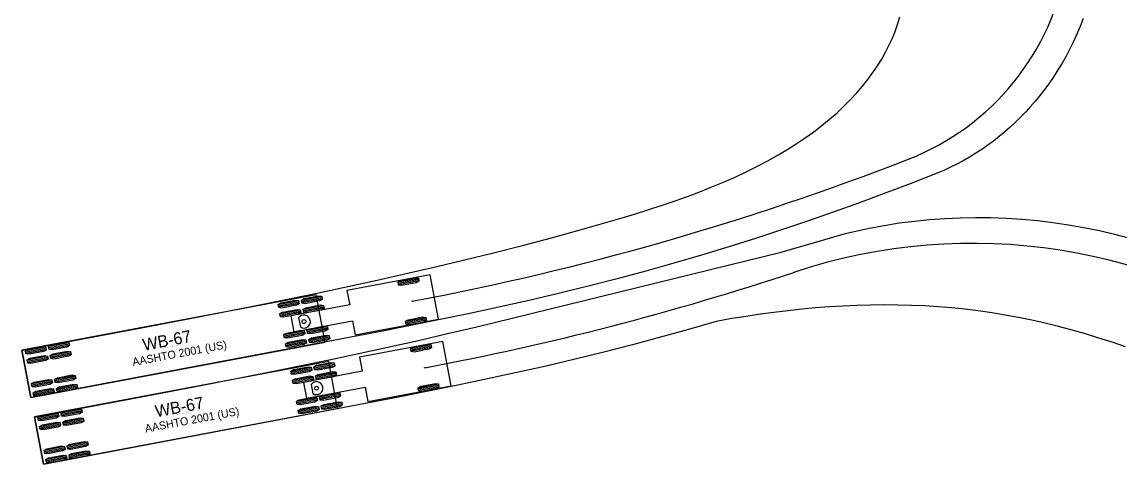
# Model space of a CAD drawing. Extents: x 1639988 to 1641860, y 841974 to 844187.
# Drawn here: x 1641354.5 to 1641548.8, y 842060.7 to 842139 of the extents above; entities that cross this region are included whole.
import ezdxf

# ---------------------------------------------------------------- set-up
doc = ezdxf.new("R2010")
doc.units = 0
doc.layers.add('Scratch_Level_1', color=7, linetype='Continuous')

msp = doc.modelspace()

# ---------------------------------------------------------------- linework, layer by layer
at = {"layer": 'Scratch_Level_1'}
for p, q in [((1641426.82, 842094.17), (1641412.08, 842091.39)), ((1641428.31, 842086.31), (1641426.82, 842094.17)), ((1641426.82, 842094.17), (1641426.82, 842094.17)), ((1641424.74, 842093.54), (1641421.13, 842092.86)), ((1641424.78, 842093.32), (1641421.18, 842092.64)), ((1641424.82, 842093.09), (1641421.22, 842092.41)), ((1641406.63, 842090.62), (1641354.55, 842080.8)), ((1641407.62, 842090.32), (1641404.02, 842089.64)), ((1641407.66, 842090.09), (1641404.06, 842089.41)), ((1641408.21, 842082.27), (1641406.63, 842090.62)), ((1641406.63, 842090.62), (1641406.63, 842090.62)), ((1641412.08, 842091.39), (1641412.56, 842088.87)), ((1641403.53, 842089.54), (1641399.92, 842088.87)), ((1641403.57, 842089.32), (1641399.97, 842088.64)), ((1641403.61, 842089.09), (1641400.01, 842088.42)), ((1641412.56, 842088.87), (1641402.16, 842086.91)), ((1641407.71, 842089.87), (1641404.1, 842089.19)), ((1641407.93, 842088.7), (1641404.32, 842088.02)), ((1641407.97, 842088.47), (1641404.37, 842087.79)), ((1641408.01, 842088.25), (1641404.41, 842087.57)), ((1641403.83, 842087.92), (1641400.23, 842087.24)), ((1641403.87, 842087.7), (1641400.27, 842087.02)), ((1641403.92, 842087.47), (1641400.31, 842086.79)), ((1641402.16, 842086.91), (1641402.69, 842084.09)), ((1641403.53, 842086.53), (1641403.83, 842084.94)), ((1641413.56, 842083.53), (1641428.31, 842086.31)), ((1641426.05, 842086.58), (1641422.45, 842085.9)), ((1641426.09, 842086.36), (1641422.49, 842085.68)), ((1641402.69, 842084.09), (1641413.09, 842086.05)), ((1641408.63, 842084.98), (1641405.02, 842084.3)), ((1641408.67, 842084.75), (1641405.07, 842084.07)), ((1641408.71, 842084.53), (1641405.11, 842083.85)), ((1641413.09, 842086.05), (1641413.56, 842083.53)), ((1641426.13, 842086.13), (1641422.53, 842085.45)), ((1641404.53, 842084.21), (1641400.93, 842083.53)), ((1641404.58, 842083.98), (1641400.97, 842083.3)), ((1641404.62, 842083.76), (1641401.01, 842083.08)), ((1641404.84, 842082.58), (1641401.24, 842081.9)), ((1641404.88, 842082.36), (1641401.28, 842081.68)), ((1641408.93, 842083.36), (1641405.33, 842082.68)), ((1641408.98, 842083.13), (1641405.37, 842082.45)), ((1641409.02, 842082.91), (1641405.42, 842082.23)), ((1641429.05, 842082.38), (1641414.31, 842079.6)), ((1641430.53, 842074.52), (1641429.05, 842082.38)), ((1641429.05, 842082.38), (1641429.05, 842082.38)), ((1641354.55, 842080.8), (1641356.12, 842072.44)), ((1641358.77, 842081.36), (1641355.16, 842080.68)), ((1641358.81, 842081.13), (1641355.21, 842080.46)), ((1641358.85, 842080.91), (1641355.25, 842080.23)), ((1641356.12, 842072.44), (1641408.21, 842082.27)), ((1641362.86, 842082.13), (1641359.26, 842081.45)), ((1641362.9, 842081.91), (1641359.3, 842081.23)), ((1641362.95, 842081.68), (1641359.34, 842081)), ((1641363.17, 842080.51), (1641359.57, 842079.83)), ((1641404.92, 842082.13), (1641401.32, 842081.45)), ((1641426.96, 842081.75), (1641423.36, 842081.07)), ((1641427, 842081.53), (1641423.4, 842080.85)), ((1641427.04, 842081.3), (1641423.44, 842080.62)), ((1641359.07, 842079.74), (1641355.47, 842079.06)), ((1641359.12, 842079.51), (1641355.51, 842078.83)), ((1641359.16, 842079.29), (1641355.56, 842078.61)), ((1641408.85, 842078.83), (1641356.77, 842069.01)), ((1641363.21, 842080.29), (1641359.61, 842079.61)), ((1641363.25, 842080.06), (1641359.65, 842079.38)), ((1641409.84, 842078.52), (1641406.24, 842077.85)), ((1641410.43, 842070.47), (1641408.85, 842078.83)), ((1641408.85, 842078.83), (1641408.85, 842078.83)), ((1641414.31, 842079.6), (1641414.78, 842077.08)), ((1641405.75, 842077.75), (1641402.15, 842077.07)), ((1641405.79, 842077.53), (1641402.19, 842076.85)), ((1641405.83, 842077.3), (1641402.23, 842076.62)), ((1641414.78, 842077.08), (1641404.38, 842075.12)), ((1641409.89, 842078.3), (1641406.28, 842077.62)), ((1641409.93, 842078.07), (1641406.33, 842077.4)), ((1641410.15, 842076.9), (1641406.55, 842076.22)), ((1641410.19, 842076.68), (1641406.59, 842076)), ((1641359.87, 842075.53), (1641356.26, 842074.85)), ((1641359.91, 842075.3), (1641356.31, 842074.62)), ((1641359.95, 842075.08), (1641356.35, 842074.4)), ((1641363.96, 842076.3), (1641360.36, 842075.62)), ((1641364, 842076.08), (1641360.4, 842075.4)), ((1641364.05, 842075.85), (1641360.44, 842075.17)), ((1641364.27, 842074.68), (1641360.66, 842074)), ((1641406.06, 842076.13), (1641402.45, 842075.45)), ((1641406.1, 842075.91), (1641402.49, 842075.23)), ((1641406.14, 842075.68), (1641402.54, 842075)), ((1641404.38, 842075.12), (1641404.91, 842072.3)), ((1641405.75, 842074.74), (1641406.05, 842073.15)), ((1641410.24, 842076.45), (1641406.63, 842075.77)), ((1641428.27, 842074.79), (1641424.67, 842074.11)), ((1641428.31, 842074.57), (1641424.71, 842073.89)), ((1641360.17, 842073.91), (1641356.57, 842073.23)), ((1641360.22, 842073.68), (1641356.61, 842073)), ((1641360.26, 842073.46), (1641356.65, 842072.78)), ((1641364.31, 842074.45), (1641360.71, 842073.78)), ((1641364.35, 842074.23), (1641360.75, 842073.55)), ((1641404.91, 842072.3), (1641415.31, 842074.26)), ((1641410.85, 842073.19), (1641407.25, 842072.51)), ((1641410.89, 842072.96), (1641407.29, 842072.28)), ((1641410.94, 842072.74), (1641407.33, 842072.06)), ((1641415.31, 842074.26), (1641415.79, 842071.74)), ((1641415.79, 842071.74), (1641430.53, 842074.52)), ((1641428.36, 842074.34), (1641424.75, 842073.66)), ((1641406.76, 842072.41), (1641403.15, 842071.73)), ((1641406.8, 842072.19), (1641403.2, 842071.51)), ((1641406.84, 842071.96), (1641403.24, 842071.28)), ((1641407.06, 842070.79), (1641403.46, 842070.11)), ((1641411.16, 842071.56), (1641407.55, 842070.88)), ((1641411.2, 842071.34), (1641407.6, 842070.66)), ((1641411.24, 842071.11), (1641407.64, 842070.43)), ((1641356.77, 842069.01), (1641358.35, 842060.65)), ((1641360.99, 842069.57), (1641357.39, 842068.89)), ((1641361.03, 842069.34), (1641357.43, 842068.66)), ((1641361.08, 842069.12), (1641357.47, 842068.44)), ((1641358.35, 842060.65), (1641410.43, 842070.47)), ((1641365.09, 842070.34), (1641361.48, 842069.66)), ((1641365.13, 842070.11), (1641361.53, 842069.44)), ((1641365.17, 842069.89), (1641361.57, 842069.21)), ((1641407.1, 842070.57), (1641403.5, 842069.89)), ((1641407.15, 842070.34), (1641403.54, 842069.66)), ((1641361.3, 842067.95), (1641357.69, 842067.27)), ((1641361.34, 842067.72), (1641357.74, 842067.04)), ((1641361.38, 842067.5), (1641357.78, 842066.82)), ((1641365.39, 842068.72), (1641361.79, 842068.04)), ((1641365.43, 842068.49), (1641361.83, 842067.81)), ((1641365.48, 842068.27), (1641361.87, 842067.59)), ((1641362.09, 842063.74), (1641358.49, 842063.06)), ((1641362.13, 842063.51), (1641358.53, 842062.83)), ((1641362.18, 842063.29), (1641358.57, 842062.61)), ((1641366.19, 842064.51), (1641362.58, 842063.83)), ((1641366.23, 842064.28), (1641362.62, 842063.6)), ((1641366.27, 842064.06), (1641362.67, 842063.38)), ((1641362.4, 842062.12), (1641358.79, 842061.44)), ((1641362.44, 842061.89), (1641358.84, 842061.21)), ((1641362.48, 842061.67), (1641358.88, 842060.99)), ((1641366.49, 842062.89), (1641362.89, 842062.21)), ((1641366.53, 842062.66), (1641362.93, 842061.98)), ((1641366.58, 842062.44), (1641362.97, 842061.76))]:
    msp.add_line(p, q, dxfattribs=at)
for points in [[(1641542.38, 842139.54), (1641541.85, 842138.16), (1641541.28, 842136.8), (1641540.68, 842135.47), (1641540.04, 842134.17), (1641539.37, 842132.9), (1641538.67, 842131.66), (1641537.94, 842130.46), (1641537.19, 842129.29), (1641536.41, 842128.16), (1641535.61, 842127.06), (1641534.79, 842126), (1641533.95, 842124.97), (1641533.09, 842123.98), (1641532.22, 842123.02), (1641531.33, 842122.1), (1641530.41, 842121.2), (1641529.47, 842120.32), (1641528.51, 842119.48), (1641527.53, 842118.66), (1641526.52, 842117.87), (1641525.5, 842117.12), (1641524.45, 842116.39), (1641523.38, 842115.69), (1641522.29, 842115.02), (1641521.18, 842114.38), (1641520.05, 842113.78), (1641518.9, 842113.21), (1641517.72, 842112.67), (1641516.53, 842112.17), (1641511.8, 842110.31), (1641507.19, 842108.56), (1641502.65, 842106.88), (1641498.13, 842105.26), (1641493.6, 842103.68), (1641489.02, 842102.14), (1641484.38, 842100.63), (1641479.66, 842099.14), (1641474.86, 842097.68), (1641469.96, 842096.25), (1641464.97, 842094.84), (1641459.9, 842093.48), (1641454.75, 842092.15), (1641449.54, 842090.87), (1641444.31, 842089.64), (1641433.82, 842087.34), (1641428.57, 842086.24), (1641423.31, 842085.17), (1641418.05, 842084.14), (1641356.12, 842072.44), (1641354.55, 842080.8), (1641354.66, 842080.82), (1641354.66, 842080.82)], [(1641354.66, 842080.82), (1641375.69, 842084.79), (1641386.17, 842086.8), (1641396.61, 842088.86), (1641401.83, 842089.91), (1641407.03, 842090.99), (1641412.22, 842092.09), (1641417.41, 842093.23), (1641422.58, 842094.39), (1641427.75, 842095.58), (1641432.9, 842096.82), (1641438.04, 842098.08), (1641443.17, 842099.39), (1641448.28, 842100.74), (1641453.35, 842102.12), (1641458.33, 842103.54), (1641460.77, 842104.26), (1641463.18, 842104.99), (1641465.54, 842105.74), (1641467.87, 842106.5), (1641470.15, 842107.28), (1641472.38, 842108.07), (1641474.56, 842108.89), (1641476.69, 842109.74), (1641478.76, 842110.6), (1641480.78, 842111.49), (1641482.74, 842112.4), (1641484.64, 842113.34), (1641486.48, 842114.31), (1641488.26, 842115.3), (1641489.97, 842116.32), (1641491.62, 842117.36), (1641493.2, 842118.42), (1641494.71, 842119.51), (1641496.15, 842120.61), (1641497.52, 842121.74), (1641498.83, 842122.88), (1641500.06, 842124.04), (1641501.22, 842125.21), (1641502.31, 842126.39), (1641503.34, 842127.58), (1641504.29, 842128.78), (1641505.17, 842129.98), (1641505.99, 842131.19), (1641506.73, 842132.39), (1641507.41, 842133.59), (1641508.02, 842134.78), (1641508.58, 842135.99), (1641509.09, 842137.24), (1641509.56, 842138.53), (1641509.97, 842139.86)], [(1641356.92, 842069.03), (1641377.9, 842073), (1641388.36, 842075), (1641398.8, 842077.05), (1641404, 842078.11), (1641409.2, 842079.18), (1641414.39, 842080.28), (1641419.57, 842081.41), (1641424.74, 842082.56), (1641429.9, 842083.75), (1641435.05, 842084.97), (1641488.95, 842098.2), (1641496.67, 842100.45), (1641499.27, 842101.19), (1641500.57, 842101.53), (1641501.89, 842101.85), (1641503.2, 842102.15), (1641504.52, 842102.43), (1641507.17, 842102.92), (1641509.84, 842103.35), (1641512.52, 842103.69), (1641515.2, 842103.96), (1641517.9, 842104.16), (1641520.6, 842104.28), (1641523.32, 842104.32), (1641526.05, 842104.3), (1641528.79, 842104.2), (1641531.54, 842104.02), (1641534.29, 842103.77), (1641537.04, 842103.44), (1641539.79, 842103.04), (1641542.53, 842102.56), (1641545.26, 842102), (1641547.97, 842101.38), (1641550.67, 842100.68)], [(1641549.91, 842081.42), (1641547.54, 842082.22), (1641545.17, 842082.98), (1641542.8, 842083.69), (1641540.43, 842084.37), (1641538.05, 842085), (1641535.68, 842085.58), (1641533.31, 842086.11), (1641530.94, 842086.6), (1641528.57, 842087.04), (1641526.21, 842087.43), (1641523.84, 842087.77), (1641521.47, 842088.06), (1641519.11, 842088.3), (1641516.75, 842088.5), (1641514.37, 842088.65), (1641511.99, 842088.76), (1641509.59, 842088.82), (1641507.19, 842088.84), (1641504.78, 842088.81), (1641502.35, 842088.74), (1641499.92, 842088.64), (1641497.49, 842088.49), (1641495.04, 842088.3), (1641492.59, 842088.07), (1641490.13, 842087.81), (1641487.67, 842087.51), (1641485.2, 842087.18), (1641482.72, 842086.81), (1641480.23, 842086.42), (1641477.43, 842085.93), (1641472.53, 842084.5), (1641467.59, 842083.12), (1641462.6, 842081.78), (1641457.56, 842080.48), (1641452.47, 842079.23), (1641447.32, 842078.02), (1641442.14, 842076.87), (1641436.93, 842075.73), (1641431.69, 842074.63), (1641426.45, 842073.56), (1641421.19, 842072.52), (1641410.67, 842070.52), (1641358.35, 842060.65), (1641356.77, 842069.01), (1641356.92, 842069.03), (1641356.92, 842069.03)]]:
    msp.add_lwpolyline(points, dxfattribs=at)
for points in [[(1641424.73, 842093.6), (1641424.83, 842093.04), (1641424.36, 842092.77), (1641421.76, 842092.28), (1641421.23, 842092.36), (1641421.12, 842092.92), (1641421.59, 842093.19), (1641424.19, 842093.67)], [(1641407.61, 842090.37), (1641407.72, 842089.81), (1641407.24, 842089.55), (1641404.65, 842089.06), (1641404.11, 842089.13), (1641404.01, 842089.69), (1641404.48, 842089.96), (1641407.07, 842090.45)], [(1641403.52, 842089.6), (1641403.62, 842089.04), (1641403.15, 842088.77), (1641400.56, 842088.29), (1641400.02, 842088.36), (1641399.91, 842088.92), (1641400.39, 842089.19), (1641402.98, 842089.68)], [(1641407.92, 842088.75), (1641408.02, 842088.19), (1641407.55, 842087.92), (1641404.96, 842087.44), (1641404.42, 842087.51), (1641404.31, 842088.07), (1641404.79, 842088.34), (1641407.38, 842088.83)], [(1641403.82, 842087.98), (1641403.93, 842087.42), (1641403.46, 842087.15), (1641400.86, 842086.66), (1641400.32, 842086.74), (1641400.22, 842087.3), (1641400.69, 842087.56), (1641403.29, 842088.05)], [(1641426.04, 842086.64), (1641426.14, 842086.08), (1641425.67, 842085.81), (1641423.08, 842085.32), (1641422.54, 842085.4), (1641422.43, 842085.96), (1641422.91, 842086.22), (1641425.5, 842086.71)], [(1641404.52, 842084.26), (1641404.63, 842083.7), (1641404.16, 842083.44), (1641401.56, 842082.95), (1641401.03, 842083.02), (1641400.92, 842083.58), (1641401.39, 842083.85), (1641403.99, 842084.34)], [(1641408.62, 842085.03), (1641408.72, 842084.47), (1641408.25, 842084.21), (1641405.66, 842083.72), (1641405.12, 842083.79), (1641405.01, 842084.35), (1641405.49, 842084.62), (1641408.08, 842085.11)], [(1641404.83, 842082.64), (1641404.93, 842082.08), (1641404.46, 842081.81), (1641401.87, 842081.32), (1641401.33, 842081.4), (1641401.23, 842081.96), (1641401.7, 842082.23), (1641404.29, 842082.71)], [(1641408.92, 842083.41), (1641409.03, 842082.85), (1641408.56, 842082.59), (1641405.96, 842082.1), (1641405.43, 842082.17), (1641405.32, 842082.73), (1641405.79, 842083), (1641408.39, 842083.49)], [(1641358.76, 842081.42), (1641358.86, 842080.85), (1641358.39, 842080.59), (1641355.8, 842080.1), (1641355.26, 842080.17), (1641355.15, 842080.74), (1641355.63, 842081), (1641358.22, 842081.49)], [(1641362.85, 842082.19), (1641362.96, 842081.63), (1641362.49, 842081.36), (1641359.89, 842080.87), (1641359.35, 842080.95), (1641359.25, 842081.51), (1641359.72, 842081.77), (1641362.32, 842082.26)], [(1641363.16, 842080.57), (1641363.26, 842080), (1641362.79, 842079.74), (1641360.2, 842079.25), (1641359.66, 842079.33), (1641359.55, 842079.89), (1641360.03, 842080.15), (1641362.62, 842080.64)], [(1641426.95, 842081.81), (1641427.05, 842081.25), (1641426.58, 842080.98), (1641423.99, 842080.49), (1641423.45, 842080.57), (1641423.35, 842081.13), (1641423.82, 842081.39), (1641426.41, 842081.88)], [(1641359.06, 842079.79), (1641359.17, 842079.23), (1641358.7, 842078.97), (1641356.1, 842078.48), (1641355.57, 842078.55), (1641355.46, 842079.12), (1641355.93, 842079.38), (1641358.53, 842079.87)], [(1641409.83, 842078.58), (1641409.94, 842078.02), (1641409.47, 842077.75), (1641406.87, 842077.26), (1641406.34, 842077.34), (1641406.23, 842077.9), (1641406.7, 842078.17), (1641409.3, 842078.65)], [(1641405.74, 842077.81), (1641405.85, 842077.25), (1641405.37, 842076.98), (1641402.78, 842076.49), (1641402.24, 842076.57), (1641402.14, 842077.13), (1641402.61, 842077.39), (1641405.2, 842077.88)], [(1641410.14, 842076.96), (1641410.25, 842076.4), (1641409.77, 842076.13), (1641407.18, 842075.64), (1641406.64, 842075.72), (1641406.54, 842076.28), (1641407.01, 842076.54), (1641409.6, 842077.03)], [(1641359.86, 842075.59), (1641359.96, 842075.02), (1641359.49, 842074.76), (1641356.9, 842074.27), (1641356.36, 842074.34), (1641356.25, 842074.91), (1641356.73, 842075.17), (1641359.32, 842075.66)], [(1641363.95, 842076.36), (1641364.06, 842075.8), (1641363.58, 842075.53), (1641360.99, 842075.04), (1641360.45, 842075.12), (1641360.35, 842075.68), (1641360.82, 842075.94), (1641363.41, 842076.43)], [(1641364.26, 842074.74), (1641364.36, 842074.17), (1641363.89, 842073.91), (1641361.3, 842073.42), (1641360.76, 842073.49), (1641360.65, 842074.06), (1641361.13, 842074.32), (1641363.72, 842074.81)], [(1641406.05, 842076.19), (1641406.15, 842075.63), (1641405.68, 842075.36), (1641403.08, 842074.87), (1641402.55, 842074.95), (1641402.44, 842075.51), (1641402.91, 842075.77), (1641405.51, 842076.26)], [(1641428.26, 842074.85), (1641428.37, 842074.28), (1641427.89, 842074.02), (1641425.3, 842073.53), (1641424.76, 842073.61), (1641424.66, 842074.17), (1641425.13, 842074.43), (1641427.73, 842074.92)], [(1641360.16, 842073.96), (1641360.27, 842073.4), (1641359.8, 842073.14), (1641357.2, 842072.65), (1641356.67, 842072.72), (1641356.56, 842073.28), (1641357.03, 842073.55), (1641359.63, 842074.04)], [(1641410.84, 842073.24), (1641410.95, 842072.68), (1641410.47, 842072.41), (1641407.88, 842071.93), (1641407.34, 842072), (1641407.24, 842072.56), (1641407.71, 842072.83), (1641410.3, 842073.32)], [(1641406.75, 842072.47), (1641406.85, 842071.91), (1641406.38, 842071.64), (1641403.79, 842071.15), (1641403.25, 842071.23), (1641403.14, 842071.79), (1641403.62, 842072.05), (1641406.21, 842072.54)], [(1641407.05, 842070.85), (1641407.16, 842070.29), (1641406.69, 842070.02), (1641404.09, 842069.53), (1641403.55, 842069.61), (1641403.45, 842070.17), (1641403.92, 842070.43), (1641406.52, 842070.92)], [(1641411.15, 842071.62), (1641411.25, 842071.06), (1641410.78, 842070.79), (1641408.19, 842070.3), (1641407.65, 842070.38), (1641407.54, 842070.94), (1641408.02, 842071.21), (1641410.61, 842071.69)], [(1641360.98, 842069.62), (1641361.09, 842069.06), (1641360.61, 842068.8), (1641358.02, 842068.31), (1641357.48, 842068.38), (1641357.38, 842068.94), (1641357.85, 842069.21), (1641360.44, 842069.7)], [(1641365.08, 842070.4), (1641365.18, 842069.83), (1641364.71, 842069.57), (1641362.11, 842069.08), (1641361.58, 842069.15), (1641361.47, 842069.72), (1641361.94, 842069.98), (1641364.54, 842070.47)], [(1641365.38, 842068.77), (1641365.49, 842068.21), (1641365.01, 842067.95), (1641362.42, 842067.46), (1641361.88, 842067.53), (1641361.78, 842068.09), (1641362.25, 842068.36), (1641364.84, 842068.85)], [(1641361.29, 842068), (1641361.39, 842067.44), (1641360.92, 842067.18), (1641358.33, 842066.69), (1641357.79, 842066.76), (1641357.68, 842067.32), (1641358.16, 842067.59), (1641360.75, 842068.08)], [(1641362.08, 842063.79), (1641362.19, 842063.23), (1641361.71, 842062.97), (1641359.12, 842062.48), (1641358.58, 842062.55), (1641358.48, 842063.11), (1641358.95, 842063.38), (1641361.54, 842063.87)], [(1641366.17, 842064.57), (1641366.28, 842064), (1641365.81, 842063.74), (1641363.21, 842063.25), (1641362.68, 842063.32), (1641362.57, 842063.89), (1641363.04, 842064.15), (1641365.64, 842064.64)], [(1641366.48, 842062.94), (1641366.59, 842062.38), (1641366.11, 842062.12), (1641363.52, 842061.63), (1641362.98, 842061.7), (1641362.88, 842062.26), (1641363.35, 842062.53), (1641365.94, 842063.02)], [(1641362.39, 842062.17), (1641362.49, 842061.61), (1641362.02, 842061.35), (1641359.43, 842060.86), (1641358.89, 842060.93), (1641358.78, 842061.49), (1641359.26, 842061.76), (1641361.85, 842062.25)]]:
    msp.add_lwpolyline(points, close=True, dxfattribs=at)
for centre, radius in [((1641511.45, 842114.65), 0.0417), ((1641511.45, 842114.65), 0.0417), ((1641491.35, 842094.66), 0.0417), ((1641491.35, 842094.66), 0.0417), ((1641423.63, 842089.5), 0.0417), ((1641404.47, 842085.89), 0.34), ((1641425.86, 842077.71), 0.0417), ((1641406.69, 842074.09), 0.34)]:
    msp.add_circle(centre, radius, dxfattribs=at)
for centre, radius, start, end in [((1641495.12, 842156.58), 45, 291.2884, 49.8888), ((1641332.1, 842574.94), 494, 280.6779, 291.2884), ((1641522.82, 841999.74), 100, 53.7861, 108.3437), ((1641332.1, 842574.94), 506, 280.6779, 288.3437), ((1641404.47, 842085.89), 1.14, 235.6779, 145.6779), ((1641406.69, 842074.09), 1.14, 235.6779, 145.6779)]:
    msp.add_arc(centre, radius, start, end, dxfattribs=at)

# ---------------------------------------------------------------- texts
for s, height, p in [('WB-67', 2.125, (1641376.13, 842080.71)), ('AASHTO 2001 (US)', 1.4167, (1641374.24, 842078.02)), ('(c) 2019 Transoft Solutions, Inc. All rights reserved.', 0.085, (1641379.68, 842081.17)), ('AASHTO 2001 (US)', 1.4167, (1641376.46, 842066.22)), ('WB-67', 2.125, (1641378.35, 842068.92)), ('(c) 2019 Transoft Solutions, Inc. All rights reserved.', 0.085, (1641381.91, 842069.38))]:
    msp.add_text(s, height=height, rotation=10.6779, dxfattribs=at).set_placement(p)

doc.saveas('drawing.dxf')
